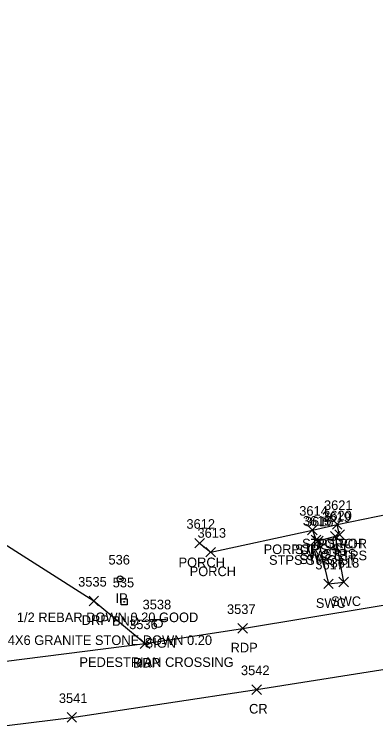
# Model space of a CAD drawing. Extents: x 1690689 to 1696275, y 438760 to 444007.
# Drawn here: x 1691383.2 to 1691458.4, y 442422.9 to 442572.4 of the extents above; entities that cross this region are included whole.
import ezdxf

# ---------------------------------------------------------------- set-up
doc = ezdxf.new("R2010")
doc.units = 0
for name, color, linetype in [('L_A', 7, 'Continuous'), ('L_I', 7, 'Continuous'), ('L_TIC', 7, 'Continuous'), ('LBF', 7, 'Continuous'), ('Level 18', 7, 'Continuous'), ('M_A', 7, 'Continuous'), ('M_C', 7, 'Continuous'), ('M_I', 7, 'Continuous'), ('MPIR', 7, 'Continuous'), ('P_A', 7, 'Continuous'), ('P_I', 7, 'Continuous'), ('P_TIC', 7, 'Continuous'), ('PET', 7, 'Continuous'), ('PRC', 7, 'Continuous'), ('R_A', 7, 'Continuous'), ('R_I', 7, 'Continuous'), ('R_TIC', 7, 'Continuous'), ('RDP', 7, 'Continuous'), ('RSW', 7, 'Continuous'), ('S_A', 7, 'Continuous'), ('S_C', 7, 'Continuous'), ('S_I', 7, 'Continuous'), ('SSGN', 7, 'Continuous')]:
    doc.layers.add(name, color=color, linetype=linetype)

msp = doc.modelspace()

# ---------------------------------------------------------------- linework, layer by layer
at = {"layer": 'L_TIC'}
for points in [[(1691449.41, 442465.12), (1691451.41, 442467.12)], [(1691451.41, 442465.12), (1691449.41, 442467.12)], [(1691449.41, 442465.12), (1691451.41, 442467.12)], [(1691451.41, 442465.12), (1691449.41, 442467.12)], [(1691444.26, 442463.94), (1691446.26, 442465.94)], [(1691446.26, 442463.94), (1691444.26, 442465.94)], [(1691444.26, 442463.94), (1691446.26, 442465.94)], [(1691446.26, 442463.94), (1691444.26, 442465.94)], [(1691449.91, 442462.97), (1691451.91, 442464.97)], [(1691451.91, 442462.97), (1691449.91, 442464.97)], [(1691445.01, 442461.86), (1691447.01, 442463.86)], [(1691447.01, 442461.86), (1691445.01, 442463.86)], [(1691445.49, 442461.7), (1691447.49, 442463.7)], [(1691447.49, 442461.7), (1691445.49, 442463.7)], [(1691449.05, 442462.66), (1691451.05, 442464.66)], [(1691451.05, 442462.66), (1691449.05, 442464.66)], [(1691420.78, 442461.21), (1691422.78, 442463.21)], [(1691422.78, 442461.21), (1691420.78, 442463.21)], [(1691423.09, 442459.34), (1691425.09, 442461.34)], [(1691425.09, 442459.34), (1691423.09, 442461.34)]]:
    msp.add_lwpolyline(points, dxfattribs=at)
at = {"layer": 'LBF'}
for points in [[(1691421.78, 442462.21), (1691424.09, 442460.34), (1691445.26, 442464.94), (1691450.41, 442466.12), (1691466.65, 442469.45), (1691465.23, 442476.83)], [(1691445.26, 442464.94), (1691446.01, 442462.86), (1691446.49, 442462.7), (1691450.05, 442463.66), (1691450.91, 442463.97), (1691450.41, 442466.12)]]:
    msp.add_lwpolyline(points, dxfattribs=at)
at = {"layer": 'Level 18'}
msp.add_lwpolyline([(1691405.44, 442450.62), (1691406.69, 442450.62), (1691406.69, 442449.37), (1691405.44, 442449.37)], close=True, dxfattribs=at)
msp.add_circle((1691406.07, 442450), 0.0833, dxfattribs=at)
at = {"layer": 'MPIR'}
for radius in [0.625, 0.0833]:
    msp.add_circle((1691405.24, 442454.76), radius, dxfattribs=at)
at = {"layer": 'P_TIC'}
for points in [[(1691429.74, 442443.46), (1691431.74, 442445.46)], [(1691431.74, 442443.46), (1691429.74, 442445.46)], [(1691409.43, 442440.3), (1691411.43, 442442.3)], [(1691411.43, 442440.3), (1691409.43, 442442.3)], [(1691432.65, 442430.72), (1691434.65, 442432.72)], [(1691434.65, 442430.72), (1691432.65, 442432.72)], [(1691394.19, 442424.91), (1691396.19, 442426.91)], [(1691396.19, 442424.91), (1691394.19, 442426.91)]]:
    msp.add_lwpolyline(points, dxfattribs=at)
at = {"layer": 'PET'}
msp.add_lwpolyline([(1691244.99, 442422.42), (1691274.8, 442426.79), (1691288.71, 442428.52), (1691321.88, 442431.22), (1691333.08, 442431.36), (1691372.74, 442436.52), (1691410.43, 442441.3), (1691430.74, 442444.46), (1691471.26, 442451.19), (1691485.27, 442453.88), (1691572.21, 442470.9), (1691593.06, 442475.96), (1691664.16, 442491.04), (1691682.81, 442495.5), (1691724.04, 442504.48), (1691768.38, 442514.48), (1691786.16, 442518.76), (1691792.23, 442520.23), (1691811.17, 442524.66), (1691956.19, 442557.56), (1691977.69, 442562.36), (1692021.28, 442572.37)], dxfattribs=at)
at = {"layer": 'PRC'}
msp.add_lwpolyline([(1691130.81, 442358.75), (1691152.44, 442373.63), (1691178.23, 442388.18), (1691209.8, 442400.63), (1691248.04, 442408.48), (1691275.24, 442412.28), (1691309.15, 442415.93), (1691347.17, 442419.98), (1691395.19, 442425.91), (1691433.65, 442431.72), (1691478.76, 442438.88), (1691513.2, 442445.49), (1691566.06, 442456.6), (1691813.76, 442512.5), (1691980.06, 442550.02), (1692039.61, 442563.23)], dxfattribs=at)
at = {"layer": 'R_TIC'}
for points in [[(1691445.49, 442461.7), (1691447.49, 442463.7)], [(1691447.49, 442461.7), (1691445.49, 442463.7)], [(1691449.05, 442462.66), (1691451.05, 442464.66)], [(1691451.05, 442462.66), (1691449.05, 442464.66)], [(1691447.61, 442452.74), (1691449.61, 442454.74)], [(1691449.61, 442452.74), (1691447.61, 442454.74)], [(1691450.79, 442453.12), (1691452.79, 442455.12)], [(1691452.79, 442453.12), (1691450.79, 442455.12)], [(1691398.77, 442449.17), (1691400.77, 442451.17)], [(1691400.77, 442449.17), (1691398.77, 442451.17)], [(1691409.43, 442440.3), (1691411.43, 442442.3)], [(1691411.43, 442440.3), (1691409.43, 442442.3)]]:
    msp.add_lwpolyline(points, dxfattribs=at)
at = {"layer": 'RDP'}
msp.add_lwpolyline([(1691358.55, 442468.95), (1691364.86, 442469.14), (1691377.18, 442464.54), (1691399.77, 442450.17), (1691410.43, 442441.3)], dxfattribs=at)
at = {"layer": 'RSW'}
msp.add_lwpolyline([(1691446.49, 442462.7), (1691448.61, 442453.74), (1691451.79, 442454.12), (1691450.05, 442463.66)], dxfattribs=at)
at = {"layer": 'SSGN'}
for p, q in [((1691411.55, 442446.28), (1691414.88, 442446.28)), ((1691413.19, 442445.45), (1691413.19, 442445.45))]:
    msp.add_line(p, q, dxfattribs=at)
msp.add_circle((1691413.19, 442445.45), 0.833, dxfattribs=at)

# ---------------------------------------------------------------- texts
at = {"layer": 'L_A'}
for s, p in [('POR STPS ST', (1691435.1, 442459.94)), ('PORCH', (1691440.88, 442459.94)), ('STPS POR', (1691443.11, 442461.12)), ('PORCH', (1691446.03, 442461.12)), ('SWC STPS', (1691442.66, 442458.66)), ('STPS', (1691447.42, 442458.97)), ('PORCH', (1691417.4, 442457.21)), ('STPS SWC ST', (1691436.23, 442457.7)), ('STPS', (1691442.53, 442457.86)), ('PORCH', (1691419.71, 442455.34))]:
    msp.add_text(s, height=2, dxfattribs=at).set_placement(p)
at = {"layer": 'L_I'}
for s, p in [('3621', (1691447.67, 442469.12)), ('3621', (1691447.67, 442469.12)), ('3614', (1691442.52, 442467.94)), ('3614', (1691442.52, 442467.94)), ('3615', (1691443.27, 442465.86)), ('3619', (1691447.3, 442466.66)), ('3620', (1691447.51, 442466.97)), ('3612', (1691419.04, 442465.21)), ('3616', (1691443.69, 442465.7)), ('3613', (1691421.34, 442463.34))]:
    msp.add_text(s, height=2, dxfattribs=at).set_placement(p)
at = {"layer": 'M_A'}
for s, p in [('IP', (1691404.28, 442449.76)), ('BND', (1691403.55, 442445))]:
    msp.add_text(s, height=2, dxfattribs=at).set_placement(p)
at = {"layer": 'M_C'}
for s, p in [('1/2 REBAR DOWN 0.20 GOOD', (1691383.76, 442445.76)), ('4X6 GRANITE STONE DOWN 0.20', (1691381.87, 442441))]:
    msp.add_text(s, height=2, dxfattribs=at).set_placement(p)
at = {"layer": 'M_I'}
for s, p in [('536', (1691402.82, 442457.76)), ('535', (1691403.7, 442453))]:
    msp.add_text(s, height=2, dxfattribs=at).set_placement(p)
at = {"layer": 'P_A'}
for s, p in [('RDP', (1691428.23, 442439.46)), ('RDP', (1691407.92, 442436.3)), ('CR', (1691432.08, 442426.72))]:
    msp.add_text(s, height=2, dxfattribs=at).set_placement(p)
at = {"layer": 'P_I'}
for s, p in [('3537', (1691427.48, 442447.46)), ('3536', (1691407.12, 442444.3)), ('3542', (1691430.39, 442434.72)), ('3541', (1691392.49, 442428.91))]:
    msp.add_text(s, height=2, dxfattribs=at).set_placement(p)
at = {"layer": 'R_A'}
for s, p in [('SWC STPS', (1691442.66, 442458.66)), ('STPS SWC ST', (1691436.23, 442457.7)), ('SWC', (1691445.97, 442448.74)), ('SWC', (1691449.15, 442449.12)), ('DRP', (1691397.26, 442445.17)), ('DRP', (1691407.92, 442436.3))]:
    msp.add_text(s, height=2, dxfattribs=at).set_placement(p)
at = {"layer": 'R_I'}
for s, p in [('3619', (1691447.3, 442466.66)), ('3616', (1691443.69, 442465.7)), ('3618', (1691449.05, 442457.12)), ('3617', (1691445.87, 442456.74)), ('3535', (1691396.51, 442453.17)), ('3536', (1691407.12, 442444.3))]:
    msp.add_text(s, height=2, dxfattribs=at).set_placement(p)
at = {"layer": 'S_A'}
msp.add_text('SIGN', height=2, dxfattribs=at).set_placement((1691410.33, 442440.43))
at = {"layer": 'S_C'}
msp.add_text('PEDESTRIAN CROSSING', height=2, dxfattribs=at).set_placement((1691396.77, 442436.43))
at = {"layer": 'S_I'}
msp.add_text('3538', height=2, dxfattribs=at).set_placement((1691409.92, 442448.43))

doc.saveas('drawing.dxf')
